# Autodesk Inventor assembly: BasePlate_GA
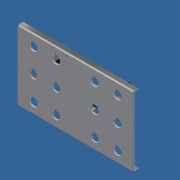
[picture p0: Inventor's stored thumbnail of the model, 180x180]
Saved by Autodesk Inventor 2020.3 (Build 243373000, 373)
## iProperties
Created: 2020-09
Part Number: BasePlate_GA
Document SubType Name: Assembly
Designer: biggshj
Mass: 59459.7 g
Surface Area: 41799.1 cm^2
Volume: 23833.4 cm^3
Density: 2.4948 g/cm^3
Author: biggshj
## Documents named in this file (12)
- C:\vaultcache\Inventor Data\Designs\Projects H\END19505 Drone Flow\Canal Deployment\BasePlate_GA.iam
- C:\vaultcache\Inventor Data\Designs\Projects H\END19505 Drone Flow\Canal Deployment\BasePlate.ipt
- C:\vaultcache\Inventor Data\Designs\Projects H\END19505 Drone Flow\Canal Deployment\BatteryCase_Bracket_SheetMetal_v2_Cradle.ipt
- C:\vaultcache\Inventor Data\Designs\Projects H\END19505 Drone Flow\Canal Deployment\BatteryCase_Bracket_SheetMetal_v2_Clamp.ipt
- C:\vaultcache\Inventor Data\Designs\Projects H\END19505 Drone Flow\Canal Deployment\Aquadopp_Bracket_SheetMetal_Clamp.ipt
- C:\vaultcache\Inventor Data\Designs\Projects H\END19505 Drone Flow\Canal Deployment\Aquadopp_Bracket_SheetMetal_Cradle.ipt
- C:\vaultcache\Inventor Data\Designs\Projects H\END19505 Drone Flow\Canal Deployment\Aquadopp_Measured.ipt
- C:\vaultcache\Inventor Data\Designs\Projects H\END19505 Drone Flow\Canal Deployment\Signature_Measured.ipt
- C:\vaultcache\Inventor Data\Designs\Projects H\END19505 Drone Flow\Canal Deployment\BatteryCase_Measured.ipt
- C:\vaultcache\Inventor Data\Designs\Projects H\END19505 Drone Flow\Canal Deployment\SkidPlate.ipt
- C:\vaultcache\Inventor Data\Designs\Projects H\END19505 Drone Flow\Canal Deployment\Signature_Z_Bracket_SheetMetal_2.ipt
- C:\vaultcache\Inventor Data\xContent Centre Files\en-US\SOCKET HEAD CSK SS DIN 7991\CSK SOCKET SCREW 316 M8x30.ipt
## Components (36 placed, 11 different names)
1. BasePlate:1 — Insert:7, Mate:25, Mate:30, Mate:54, Mate:55, Mate:56, Mate:59, Mate:60, Mate:61, Mate:62, Insert:2, Mate:63, Insert:8
2. BatteryCase_Bracket_SheetMetal_v2_Cradle:1 — Insert:7, Mate:9, Mate:10, Mate:44, Mate:45
3. BatteryCase_Bracket_SheetMetal_v2_Clamp:1 — Mate:11, Mate:44
4. Aquadopp_Measured:1 — Mate:28, Mate:33, Flush:1, Mate:53
5. Signature_Measured:1 — Insert:1, Mate:57
6. BatteryCase_Measured:1 — Mate:9, Mate:10, Mate:11, Mate:14, Mate:15, Mate:45
7. BatteryCase_Bracket_SheetMetal_v2_Cradle:2 — Mate:15, Mate:38, Mate:39, Insert:2, Mate:63
8. BatteryCase_Bracket_SheetMetal_v2_Clamp:2 — Mate:14, Mate:38, Mate:39
9. Aquadopp_Bracket_SheetMetal_Clamp:2 — Mate:33, Mate:51, Mate:52
10. Aquadopp_Bracket_SheetMetal_Cradle:2 — Mate:30, Mate:51, Mate:52
11. Aquadopp_Bracket_SheetMetal_Clamp:3 — Mate:28, Mate:43, Mate:48, Flush:1
12. Aquadopp_Bracket_SheetMetal_Cradle:3 — Mate:25, Mate:43, Mate:48, Mate:53
13. SkidPlate:1 — Mate:54, Mate:55, Mate:56
14. SOCKET HEAD CSK SS DIN 7991 M8x30:1
15. SOCKET HEAD CSK SS DIN 7991 M8x30:2
16. SOCKET HEAD CSK SS DIN 7991 M8x30:3
17. SOCKET HEAD CSK SS DIN 7991 M8x30:4
18. SOCKET HEAD CSK SS DIN 7991 M8x30:5
19. SOCKET HEAD CSK SS DIN 7991 M8x30:6
20. SOCKET HEAD CSK SS DIN 7991 M8x30:7
21. SOCKET HEAD CSK SS DIN 7991 M8x30:8
22. SOCKET HEAD CSK SS DIN 7991 M8x30:9
23. SOCKET HEAD CSK SS DIN 7991 M8x30:10
24. SOCKET HEAD CSK SS DIN 7991 M8x30:11
25. SOCKET HEAD CSK SS DIN 7991 M8x30:12
26. SOCKET HEAD CSK SS DIN 7991 M8x30:13
27. SOCKET HEAD CSK SS DIN 7991 M8x30:14
28. SOCKET HEAD CSK SS DIN 7991 M8x30:15
29. SOCKET HEAD CSK SS DIN 7991 M8x30:16
30. SOCKET HEAD CSK SS DIN 7991 M8x30:17
31. SOCKET HEAD CSK SS DIN 7991 M8x30:18
32. SOCKET HEAD CSK SS DIN 7991 M8x30:19
33. SOCKET HEAD CSK SS DIN 7991 M8x30:20
34. SOCKET HEAD CSK SS DIN 7991 M8x30:21
35. Signature_Z_Bracket_SheetMetal_2:1 — Insert:1, Mate:57, Mate:62, Angle:3
36. Signature_Z_Bracket_SheetMetal_2:2 — Insert:8
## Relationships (33: Mate 27, Insert 4, Flush 1, Angle 1)
- Insert:7: BasePlate:1 ↔ BatteryCase_Bracket_SheetMetal_v2_Cradle:1
- Mate:9: BatteryCase_Bracket_SheetMetal_v2_Cradle:1 ↔ BatteryCase_Measured:1
- Mate:10: BatteryCase_Bracket_SheetMetal_v2_Cradle:1 ↔ BatteryCase_Measured:1
- Mate:11: BatteryCase_Bracket_SheetMetal_v2_Clamp:1 ↔ BatteryCase_Measured:1
- Mate:14: BatteryCase_Measured:1 ↔ BatteryCase_Bracket_SheetMetal_v2_Clamp:2
- Mate:15: BatteryCase_Measured:1 ↔ BatteryCase_Bracket_SheetMetal_v2_Cradle:2
- Mate:25: BasePlate:1 ↔ Aquadopp_Bracket_SheetMetal_Cradle:3
- Mate:28: Aquadopp_Measured:1 ↔ Aquadopp_Bracket_SheetMetal_Clamp:3
- Mate:30: BasePlate:1 ↔ Aquadopp_Bracket_SheetMetal_Cradle:2
- Mate:33: Aquadopp_Measured:1 ↔ Aquadopp_Bracket_SheetMetal_Clamp:2
- Mate:38: BatteryCase_Bracket_SheetMetal_v2_Cradle:2 ↔ BatteryCase_Bracket_SheetMetal_v2_Clamp:2
- Mate:39: BatteryCase_Bracket_SheetMetal_v2_Cradle:2 ↔ BatteryCase_Bracket_SheetMetal_v2_Clamp:2
- Mate:43: Aquadopp_Bracket_SheetMetal_Clamp:3 ↔ Aquadopp_Bracket_SheetMetal_Cradle:3
- Mate:44: BatteryCase_Bracket_SheetMetal_v2_Cradle:1 ↔ BatteryCase_Bracket_SheetMetal_v2_Clamp:1
- Mate:45: BatteryCase_Bracket_SheetMetal_v2_Cradle:1 ↔ BatteryCase_Measured:1
- Mate:48: Aquadopp_Bracket_SheetMetal_Clamp:3 ↔ Aquadopp_Bracket_SheetMetal_Cradle:3
- Mate:51: Aquadopp_Bracket_SheetMetal_Clamp:2 ↔ Aquadopp_Bracket_SheetMetal_Cradle:2
- Mate:52: Aquadopp_Bracket_SheetMetal_Clamp:2 ↔ Aquadopp_Bracket_SheetMetal_Cradle:2
- Flush:1: Aquadopp_Measured:1 ↔ Aquadopp_Bracket_SheetMetal_Clamp:3
- Mate:53: Aquadopp_Measured:1 ↔ Aquadopp_Bracket_SheetMetal_Cradle:3
- Mate:54: BasePlate:1 ↔ SkidPlate:1
- Mate:55: BasePlate:1 ↔ SkidPlate:1
- Mate:56: BasePlate:1 ↔ SkidPlate:1
- Insert:1: Signature_Measured:1 ↔ Signature_Z_Bracket_SheetMetal_2:1
- Mate:57: Signature_Measured:1 ↔ Signature_Z_Bracket_SheetMetal_2:1
- Mate:59: BasePlate:1
- Mate:60: BasePlate:1
- Mate:61: BasePlate:1
- Mate:62: BasePlate:1 ↔ Signature_Z_Bracket_SheetMetal_2:1
- Angle:3: Signature_Z_Bracket_SheetMetal_2:1
- Insert:2: BasePlate:1 ↔ BatteryCase_Bracket_SheetMetal_v2_Cradle:2
- Mate:63: BasePlate:1 ↔ BatteryCase_Bracket_SheetMetal_v2_Cradle:2
- Insert:8: BasePlate:1 ↔ Signature_Z_Bracket_SheetMetal_2:2
